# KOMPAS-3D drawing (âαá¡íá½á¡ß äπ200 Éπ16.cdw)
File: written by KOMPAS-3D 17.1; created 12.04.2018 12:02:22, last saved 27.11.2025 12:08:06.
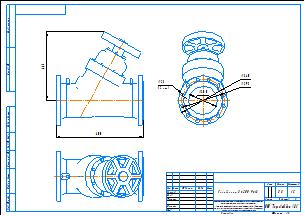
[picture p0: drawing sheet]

Sheet 1: A3, landscape

Title block, sheet 1: name: Гранбаланс Ду200 Ру16; material: Сталь 20  ГОСТ 1050-88; mass: 88; sheets: 1; sheet format: A3; stored path: C:\Users\kka\KOMPAS_Work\!Trash\КМ125 КМ127 КМ225Ф Двухходовые клапана\КМ125Ф + PSL\KOMPAS 2D\Гранрег КМ125Ф Ду32 Ру16.cdw

Views: Спереди 1, Спереди
Referenced files in C:\Users\mipv\Desktop\КБЧ\Имеющиеся\: Гранбаланс Ду200 Ру16  серия 10.m3d
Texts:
  kka
  adl
  Рама для чертежей
  Лит-Масса-Масштаб
  Материал-Предприятие
  Масштаб
  Изм.
  Лист
  № докум.
  Подп.
  Дата
  Лит.
  Разраб.
  Пров.
  Т.контр.
  Листов
  Внимание! Данный продукт является объектом авторского права ООО «Торговый Дом АДЛ».
  Запрещается изменение, копирование, распространение
  (в том числе путем копирования на другие сайты и ресурсы в Интернете)
  или любое иное использование информации и объектов без предварительного
  согласия правообладателя (ООО «Торговый Дом АДЛ»).
  Н.контр.
  Утв.
  ООО "Торговый дом АДЛ"
  Изменение
  Номер документа
  Подпись
  Обозначение документа
  Наименование изделия
  Масса изделия по ГОСТ 2.109-73
  Порядковый номер листа
  Общее количество листов в документе
  Характер работы, выполненной лицом, подписавшим документ
  Наименование или индекс предприятия, выпускающего документ
  Инв. № подл.
  Подп. и дата
  Взам. инв. №
  Инв. № дубл.
  Инвентарный номер подлинника по ГОСТ 2.501-68
  Подпись принявшего подлинник в отдел технической документации
  Инвентарный номер подлинника, взамен которого выпущен данный подлинник
  Инвентарный номер дубликата по ГОСТ 2.502-68
  Подпись принявшего дубликат в отдел технической документации
  Справ. №
  Перв. примен.
  Обозначение документа, взамен или на основании которого выпущен данный документ
  Обозначение документа, в котором впервые записан данный документ
  Подпись лица, копировавшего чертеж
  Обозначение формата листа
  !Рама для чертежа
Dimensions and other numbers on the sheet: 600; 446; 1:5; 1; 88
